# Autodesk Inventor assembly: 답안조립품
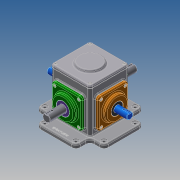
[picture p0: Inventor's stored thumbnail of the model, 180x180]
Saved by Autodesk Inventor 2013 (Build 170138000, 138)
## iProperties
Created: 2019-12
Part Number: 답안조립품
Document SubType Name: Assembly
Designer: Administrator
Author: Administrator
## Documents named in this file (16)
- C:\Users\Administrator\Desktop\391204V1017\답안조립품.iam
- C:\Users\Administrator\Desktop\391204V1017\391204V1017\개스킷.ipt
- C:\Users\Administrator\Desktop\391204V1017\391204V1017\메인베벨기어.ipt
- C:\Users\Administrator\Desktop\391204V1017\391204V1017\메인축.ipt
- C:\Users\Administrator\Desktop\391204V1017\391204V1017\메인커버.ipt
- C:\Users\Administrator\Desktop\391204V1017\391204V1017\베어링 6203.ipt
- C:\Users\Administrator\Desktop\391204V1017\391204V1017\베어링 6204.ipt
- C:\Users\Administrator\Desktop\391204V1017\391204V1017\본체.ipt
- C:\Users\Administrator\Desktop\391204V1017\391204V1017\볼트 M4.ipt
- C:\Users\Administrator\Desktop\391204V1017\391204V1017\상부커버.ipt
- C:\Users\Administrator\Desktop\391204V1017\391204V1017\서브베벨기어.ipt
- C:\Users\Administrator\Desktop\391204V1017\391204V1017\서브축.ipt
- C:\Users\Administrator\Desktop\391204V1017\391204V1017\서브커버.ipt
- C:\Users\Administrator\Desktop\391204V1017\391204V1017\오일 실 17 32 8.ipt
- C:\Users\Administrator\Desktop\391204V1017\391204V1017\오일 실 20 35 8.ipt
- C:\Users\Administrator\Desktop\391204V1017\391204V1017\키 4x4.ipt
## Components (1 placed, 1 different names)
1. 개스킷:1
